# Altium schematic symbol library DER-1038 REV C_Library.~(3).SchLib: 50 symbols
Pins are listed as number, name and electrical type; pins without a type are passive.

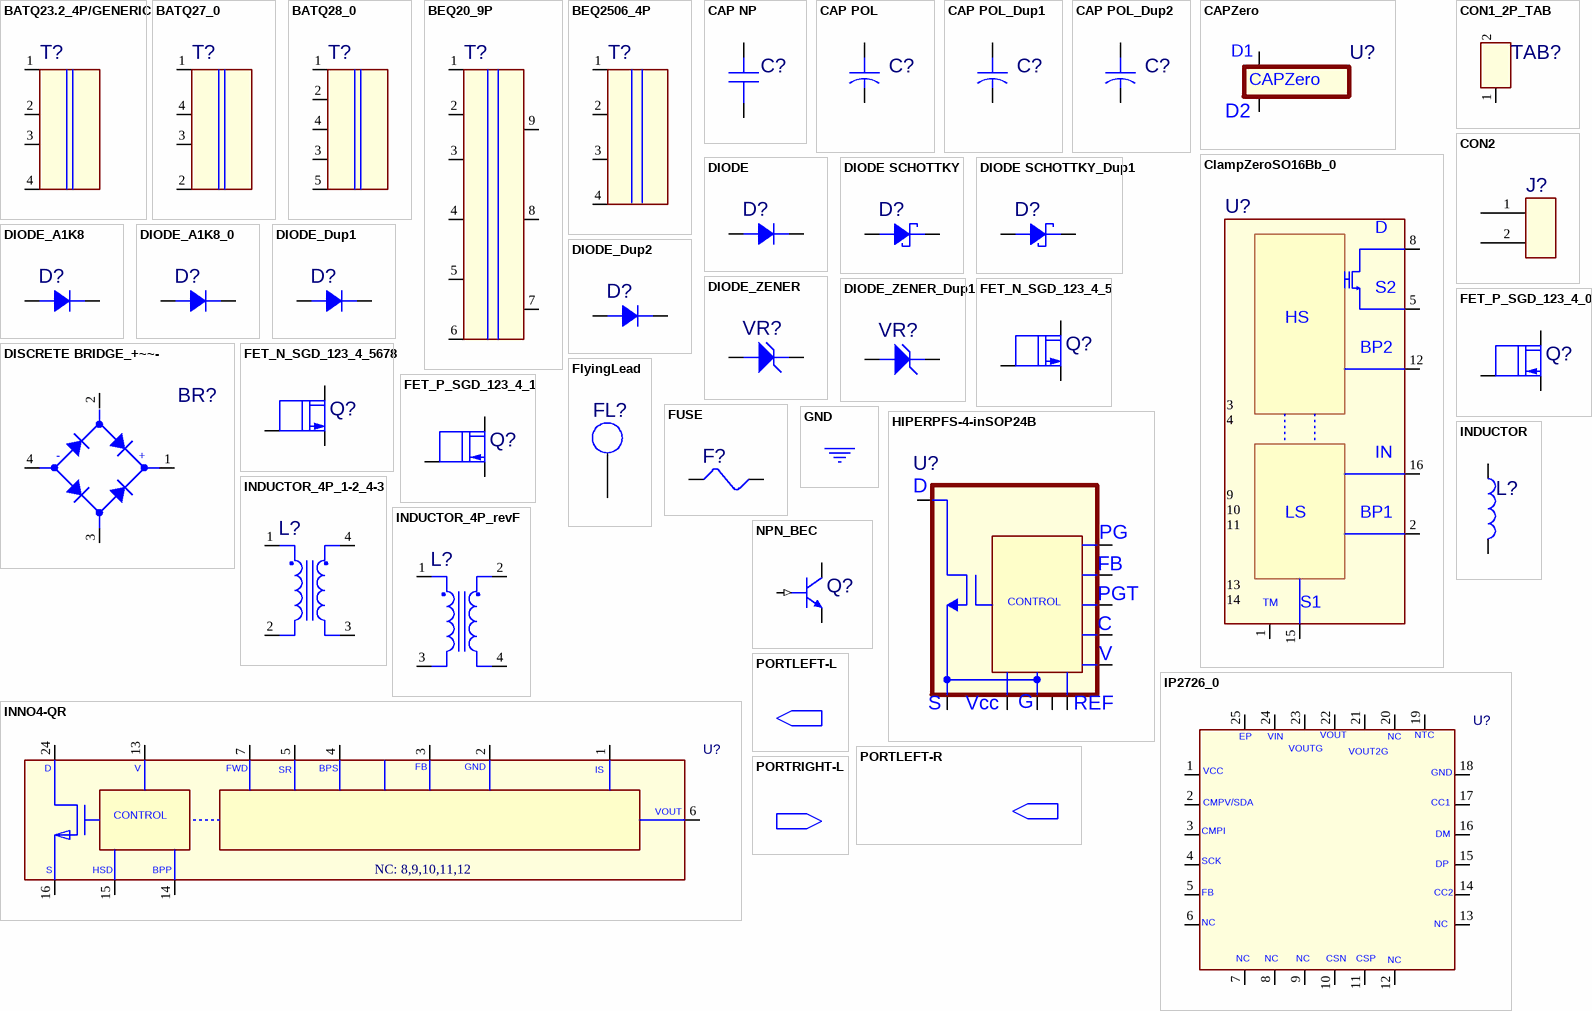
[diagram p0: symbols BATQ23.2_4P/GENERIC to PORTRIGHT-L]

## BATQ23.2_4P/GENERIC
designator T?
Altium-Right: 40; Altium-Bottom: 80
pins: 1, 2, 3, 4

## BATQ27_0
designator T?
Altium-Right: 40; Altium-Bottom: 80
pins: 1, 2, 3, 4

## BATQ28_0
designator T?
Altium-Right: 40; Altium-Bottom: 80
pins: 1, 2, 3, 4, 5

## BEQ20_9P
designator T?
Altium-Right: 40; Altium-Bottom: 181
pins: 1, 2, 3, 4, 5, 6, 7, 8, 9

## BEQ2506_4P
designator T?
Altium-Right: 40; Altium-Bottom: 90
pins: 1, 2, 3, 4

## CAP NP
designator C?
Altium-Right: 20; Altium-Bottom: 30
footprint RAD/.250X.125/LS.200/.031
pins: 1, 2

## CAP POL
designator C?
Altium-Right: 20
pins: 1, 2

## CAP POL_Dup1
designator C?
Altium-Right: 20
pins: 1, 2

## CAP POL_Dup2
designator C?
Altium-Right: 20
pins: 1, 2

## CAPZero
designator U?
Altium-Right: 70; Altium-Bottom: 20
pins: 1 NC1, 2 D1, 3 NC2, 4 NC3, 5 NC4, 6 NC5, 7 D2, 8 NC8

## ClampZeroSO16Bb_0
designator U?
PACK_SHORT: (S2,S9,S10,S11); Altium-Right: 120; Altium-Bottom: 270
pins: 1 TRIM, 2 BP1, 3 NC3, 4 NC4, 5 S2, 8 D, 9 S9, 10 S10, 11 S11, 12 BP2, 13 NC13, 14 NC14, 15 S1, 16 IN

## CON1_2P_TAB
designator TAB?  (value not drawn)
PACK_SHORT: (1,2); Altium-Right: 20; Altium-Bottom: 30
pins: 1, 2

## CON2
designator J?  (value not drawn)
Altium-Right: 20; Altium-Bottom: 40
pins: 1, 2

## DIODE
designator D?
Altium-Right: 30; Altium-Bottom: 20
pins: 1, 2

## DIODE SCHOTTKY
designator D?
Altium-Right: 30; Altium-Bottom: 20
footprint DAX1/.500X.225/.062
pins: 1, 2

## DIODE SCHOTTKY_Dup1
designator D?
Altium-Right: 30; Altium-Bottom: 20
footprint DAX1/.500X.225/.062
pins: 1, 2

## DIODE_A1K8
designator D?
Altium-Right: 30; Altium-Bottom: 20
pins: 1 A, 8 K

## DIODE_A1K8_0
designator D?
Altium-Right: 30; Altium-Bottom: 20
pins: 1 A, 8 K

## DIODE_Dup1
designator D?
Altium-Right: 30; Altium-Bottom: 20
pins: 1, 2

## DIODE_Dup2
designator D?
Altium-Right: 30; Altium-Bottom: 20
pins: 1, 2

## DIODE_ZENER
designator VR?
Altium-Right: 30; Altium-Bottom: 20
footprint DIO/W.80/LS.400/.030
pins: 1, 2

## DIODE_ZENER_Dup1
designator VR?
Altium-Right: 30; Altium-Bottom: 20
footprint DIO/W.80/LS.400/.030
pins: 1, 2

## DISCRETE BRIDGE_+~~-
designator BR?
Altium-Right: 80
pins: 1 +DC, 2 AC1, 3 AC2, 4 -DC

## FET_N_SGD_123_4_5
designator Q?
PACK_SHORT: (S,S2,S3); Altium-Right: 30; Altium-Bottom: 20
pins: 1 S, 2 S2, 3 S3, 4 G, 5 D

## FET_N_SGD_123_4_5678
designator Q?
PACK_SHORT: (S,S2,S3)(D,D6,D7,D8); Altium-Right: 30; Altium-Bottom: 20
pins: 1 S, 2 S2, 3 S3, 4 G, 5 D, 6 D6, 7 D7, 8 D8

## FET_P_SGD_123_4_0
designator Q?
PACK_SHORT: (S,S2,S3)(D,D6,D7,D8); Altium-Right: 30; Altium-Bottom: 20
pins: 1 S, 2 S2, 3 S3, 4 G, 5 D, 6 D6, 7 D7, 8 D8

## FET_P_SGD_123_4_1
designator Q?
PACK_SHORT: (S,S2,S3)(D,D6,D7,D8); Altium-Right: 30; Altium-Bottom: 20
pins: 1 S, 2 S2, 3 S3, 4 G, 5 D, 6 D6, 7 D7, 8 D8

## FlyingLead
designator FL?  (value not drawn)
Altium-Right: 20
pins: 1

## FUSE
designator F?
Altium-Right: 30; Altium-Bottom: 20
pins: 1, 2

## GND
designator *  (value not drawn)  (graphical)
Altium-Right: 20; Altium-Bottom: 10
pins: $PIN0 (power) hidden to $PIN0

## HIPERPFS-4-inSOP24B
designator U?
PACK_SHORT: (G,G12); NC: 9,10,11,13,14,15; Altium-Right: 110; Altium-Bottom: 140
pins: 1 VCC, 2 G, 3 REF, 4 V, 5 C, 6 FB, 7 PG, 8 PGT, 12 G12, 16 D, 24 S

## INDUCTOR
designator L?
Altium-Right: 10; Altium-Bottom: 40
pins: 1, 2

## INDUCTOR_4P_1-2_4-3
designator L?
Altium-Right: 40; Altium-Bottom: 60
pins: 1, 2, 3, 4

## INDUCTOR_4P_revF
designator L?
Altium-Right: 40; Altium-Bottom: 60
pins: 1, 2, 3, 4

## INNO4-QR
designator U?  NC: 8,9,10,11,12
Altium-Right: 440; Altium-Bottom: 80
pins: 1, 2, 3, 4, 5, 6, 7, 13, 14, 15, 16, 24

## IP2726_0
designator U?
Altium-Right: 170; Altium-Bottom: 160
pins: 1, 2, 3, 4, 5, 6, 7, 8, 9, 10, 11, 12, 13, 14, 15, 16, 17, 18, 19, 20, 21, 22, 23, 24, 25

## NPN_BEC
designator Q?
Altium-Right: 20
pins: 1 BASE (in), 2 EMITTER, 3 COLLECTOR

## PORTLEFT-L
designator *  (value not drawn)  (graphical)
Altium-Right: 30; Altium-Bottom: 20
pins: PORTLEFT-L (out)

## PORTLEFT-R
designator *  (value not drawn)  (graphical)
Altium-Right: 30; Altium-Bottom: 20
pins: PORTLEFT-R (out)

## PORTRIGHT-L
designator *  (value not drawn)  (graphical)
Altium-Right: 30; Altium-Bottom: 20
pins: PORTRIGHT-L (in)

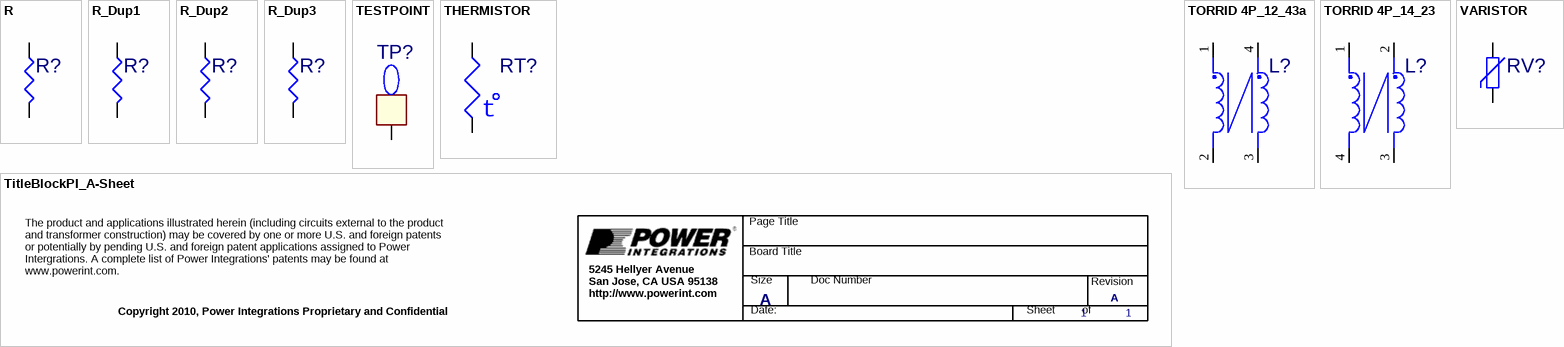
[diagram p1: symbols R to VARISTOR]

## R
designator R?
Altium-Right: 20; Altium-Bottom: 30
pins: 1, 2

## R_Dup1
designator R?
Altium-Right: 20; Altium-Bottom: 30
pins: 1, 2

## R_Dup2
designator R?
Altium-Right: 20; Altium-Bottom: 30
pins: 1, 2

## R_Dup3
designator R?
Altium-Right: 20; Altium-Bottom: 30
pins: 1, 2

## TESTPOINT
designator TP?  (value not drawn)
Altium-Right: 20; Altium-Bottom: 40
pins: 1

## THERMISTOR
designator RT?
Altium-Right: 30; Altium-Bottom: 40
pins: 1, 2

## TitleBlockPI_A-Sheet
designator *  RevCode: A  Page Count: 1  (hidden comment: *)  (graphical)
Altium-Right: 760; Altium-Bottom: 70

## TORRID 4P_12_43a
designator L?
Altium-Right: 40; Altium-Bottom: 60
pins: 1, 2, 3, 4

## TORRID 4P_14_23
designator L?
Altium-Right: 40; Altium-Bottom: 60
pins: 1, 2, 3, 4

## VARISTOR
designator RV?
Altium-Right: 20
pins: 1, 2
